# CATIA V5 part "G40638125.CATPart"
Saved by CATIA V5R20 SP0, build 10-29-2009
Part number: G40638125
Revision: 5
Definition: design
Nomenclature: G40638125
Source: made
Description: NOT SPECIFIED
Bounding box of the stored display mesh (mm): x -62.5 to 62.5, y -38 to 0, z -12.5 to 12.5
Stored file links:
  C:\Users\Raffaele\Desktop\3D X SITO CF\BOLEX\30-GUIDE STRIP REF 406\G40638125.CATPart
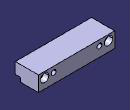
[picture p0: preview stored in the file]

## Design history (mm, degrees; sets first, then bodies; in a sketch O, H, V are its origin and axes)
Body1 "MANIFOLD_SOLID_BREP #3688" (main body)
  Solid1: solid without history
Body2 "MANIFOLD_SOLID_BREP #3826"
  Solid2: solid without history
Body3 "MANIFOLD_SOLID_BREP #3964"
  Solid3: solid without history
Body4 "MANIFOLD_SOLID_BREP #4102"
  Solid4: solid without history
Body5 "MANIFOLD_SOLID_BREP #4240"
  Solid5: solid without history
Body6 "MANIFOLD_SOLID_BREP #4378"
  Solid6: solid without history
Body7 "MANIFOLD_SOLID_BREP #4490"
  Solid7: solid without history
Body8 "MANIFOLD_SOLID_BREP #4602"
  Solid8: solid without history
Body9 "MANIFOLD_SOLID_BREP #4714"
  Solid9: solid without history
Body10 "MANIFOLD_SOLID_BREP #4826"
  Solid10: solid without history
Body11 "MANIFOLD_SOLID_BREP #4938"
  Solid11: solid without history
Body12 "MANIFOLD_SOLID_BREP #5050"
  Solid12: solid without history
Body13 "MANIFOLD_SOLID_BREP #5188"
  Solid13: solid without history
Body14 "MANIFOLD_SOLID_BREP #5326"
  Solid14: solid without history
Body15 "MANIFOLD_SOLID_BREP #5438"
  Solid15: solid without history
Body16 "MANIFOLD_SOLID_BREP #5550"
  Solid16: solid without history
Body17 "MANIFOLD_SOLID_BREP #5662"
  Solid17: solid without history
Body18 "MANIFOLD_SOLID_BREP #5774"
  Solid18: solid without history
Body19 "MANIFOLD_SOLID_BREP #5886"
  Solid19: solid without history
Body20 "MANIFOLD_SOLID_BREP #5998"
  Solid20: solid without history
Body21 "MANIFOLD_SOLID_BREP #6110"
  Solid21: solid without history
Body22 "MANIFOLD_SOLID_BREP #6222"
  Solid22: solid without history
Body23 "MANIFOLD_SOLID_BREP #6334"
  Solid23: solid without history
Body24 "MANIFOLD_SOLID_BREP #6446"
  Solid24: solid without history
Body25 "MANIFOLD_SOLID_BREP #6584"
  Solid25: solid without history
Body26 "MANIFOLD_SOLID_BREP #6722"
  Solid26: solid without history
Body27 "MANIFOLD_SOLID_BREP #6834"
  Solid27: solid without history
Body28 "MANIFOLD_SOLID_BREP #6946"
  Solid28: solid without history
Body29 "MANIFOLD_SOLID_BREP #7058"
  Solid29: solid without history
Body30 "MANIFOLD_SOLID_BREP #7170"
  Solid30: solid without history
